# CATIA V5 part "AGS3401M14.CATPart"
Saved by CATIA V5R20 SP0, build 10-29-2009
Part number: AGS3401M14
Definition: NONE
Nomenclature: AGS3401M14
Source: Unknown
Description: AGS3401M14
Bounding box of the stored display mesh (mm): x -20 to 35, y -12.5 to 12.5, z -10 to 10
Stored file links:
  C:\Users\Utente\Desktop\IO LAVORO\3D X SITO CF\X SITO\PLASTICA\AGS\AGS3401M14.CATPart
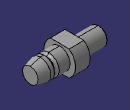
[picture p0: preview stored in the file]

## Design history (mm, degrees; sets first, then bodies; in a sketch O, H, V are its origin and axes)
Body1 "AGS3401M14" (main body)
  Solid1: solid without history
